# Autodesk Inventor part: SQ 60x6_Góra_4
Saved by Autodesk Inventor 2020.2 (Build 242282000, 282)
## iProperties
Created: 2006-08
Part Number: SQ 60x6_Góra_4
Material: Ogólny
Document SubType Name: Modeling
Designer: F.Stasiak
Manufacturer: Standard
Standards Organization: Custom
Stock Number: DIN EN 10210-2 SQ 60x6
Density: 1 g/cm^3
Appearance: Domyślna
Manager: www.cadconsulting.pl
Company: Fabian Stasiak CAD Consulting
G_L: 1000,0 mm
G_W: 60,000 mm
G_H: 60,000 mm
AFG_Item: 60 x 60 x 6
Author: F.Stasiak
Subject: Zbiór ćwiczeń. Autodesk Inventor 2020. Kurs podstawowy
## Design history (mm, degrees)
sketch "AFG_Detailed"
  geometry: L1 (48, 54)-(12, 54); L2 (6, 48)-(6, 12); L3 (12, 6)-(48, 6); L4 (54, 12)-(54, 48); L5 (48, 60)-(12, 60); L6 (0, 48)-(0, 12); L7 (12, 0)-(48, 0); L8 (60, 12)-(60, 48); A1 r 6 centre (48, 48) between (54, 48) and (48, 54); A2 r 12 centre (48, 48) between (60, 48) and (48, 60); A3 r 6 centre (48, 12) between (48, 6) and (54, 12); A4 r 12 centre (48, 12) between (48, 0) and (60, 12); A5 r 12 centre (12, 12) between (0, 12) and (12, 0); A6 r 6 centre (12, 12) between (6, 12) and (12, 6); A7 r 6 centre (12, 48) between (12, 54) and (6, 48); A8 r 12 centre (12, 48) between (12, 60) and (0, 48); 4 further points
  constraints: 16 end point, 16 point on circle, 16 tangent, 8 centre point, 6 point on line, 4 parallel, 2 perpendicular, 1 vertical
  dimensions: "d15" = 60 distance of point (0, 0) point (60, 0) (= GEO_B); "d16" = 6 distance between parallel lines of L7 L3 (= GEO_S); "d17" = 6 distance between parallel lines of L8 L4 (= GEO_S); "d18" = 6 distance between parallel lines of L5 L1 (= GEO_S); "d19" = 6 distance between parallel lines of L6 L2 (= GEO_S); "d20" = 30 distance from line of point (30, 30) L7 (= 0.5 x GEO_H); "d30" = 6 radius of A1 (= GEO_R1 - GEO_S); "GEO_R1" = 12 radius of A2; "d32" = 6 radius of A3 (= GEO_R1 - GEO_S); "d33" = 12 radius of A4 (= GEO_R1); "d34" = 12 radius of A5 (= GEO_R1); "d35" = 6 radius of A6 (= GEO_R1 - GEO_S); "d36" = 6 radius of A7 (= GEO_R1 - GEO_S); "d37" = 12 radius of A8 (= GEO_R1); "d38" = 30 distance from line of L6 point (30, 30) (= 0.5 x GEO_B); "d39" = 60 distance between parallel lines of L7 L5 (= GEO_H)
sketch "AFG_Medium"
  geometry: L1 (54, 54)-(6, 54); L2 (6, 54)-(6, 6); L3 (6, 6)-(54, 6); L4 (54, 6)-(54, 54); L5 (60, 60)-(0, 60); L6 (0, 60)-(0, 0); L7 (0, 0)-(60, 0); L8 (60, 0)-(60, 60); 1 further point
  constraints: 16 end point, 4 parallel, 2 perpendicular, 1 vertical
  dimensions: "GEO_B" = 60 distance of L6.end L7.end; "GEO_S" = 6 distance between parallel lines of L7 L3; "d5" = 6 distance between parallel lines of L8 L4 (= GEO_S); "d6" = 6 distance between parallel lines of L5 L1 (= GEO_S); "d7" = 6 distance between parallel lines of L6 L2 (= GEO_S); "d12" = 30 distance from line of point (30, 30) L7 (= 0.5 x GEO_H); "d40" = 60 distance between parallel lines of L7 L5 (= GEO_H); "d41" = 30 distance from line of L6 point (30, 30) (= 0.5 x GEO_B)
sketch "AFG_Simplified"
  geometry: L1 (60, 60)-(0, 60); L2 (0, 60)-(0, 0); L3 (0, 0)-(60, 0); L4 (60, 0)-(60, 60); 1 further point
  constraints: 8 end point, 2 parallel, 1 perpendicular, 1 vertical
  dimensions: "d23" = 60 distance of L2.end L3.end (= GEO_B); "d28" = 30 distance from line of point (30, 30) L3 (= 0.5 x GEO_H); "d42" = 60 distance between parallel lines of L3 L1 (= GEO_H); "d43" = 30 distance from line of point (30, 30) L2 (= 0.5 x GEO_B)
derived "Szkielet podstawy.ipt"
  sketch "Szkic1"
    geometry: L1 (0, 0)-(1500, 0) reference; L2 (1500, 0)-(1500, 1000) reference; L3 (1500, 1000)-(0, 1000) reference; L4 (0, 1000)-(0, 0) reference
  sketch "Szkic2"
    geometry: L1 (0, 1000)-(0, 0) reference; L2 (0, 0)-(1500, 0) reference; L3 (1500, 0)-(1500, 1000) reference; L4 (500, 1000)-(1500, 1000) reference; L5 (1500, 1000)-(1500, 0) reference; L6 (1500, 0)-(500, 0) reference; L7 (500, 0)-(500, 1000) reference; L8 (1500, 1000)-(0, 1000) reference
node "AFG_StartWorkPoint_SQ 60x6_Góra_4"
node "AFG_EndWorkPoint_SQ 60x6_Góra_4"
node "AFG_HelpAxis"
node "AFG_HelpStart"
node "AFG_HelpEnd"
node "AFG_Midplane"
  node "AFG_Startplane"
  node "AFG_EndPlane"
node "AFG_Profile_AxisX_for_External_Matrix"
extrude "AFG_Detailed_SQ 60x6_Góra_4" join sketch "AFG_Detailed" stored distance "d49" = 0.13; taper "d50" = 0 deg
extrude "AFG_Simplified_SQ 60x6_Góra_4" join sketch "AFG_Simplified" stored distance "d51" = 0.13; taper "d52" = 0 deg
node "AFG_StartWorkPoint_SQ 60x6_Góra_3"
node "AFG_EndWorkPoint_SQ 60x6_Góra_3"
node "AFG_STARTCUTPLANE_SQ 60x6_Góra_4"
node "AFG_StartWorkPoint_SQ 60x6_Góra_1"
node "AFG_EndWorkPoint_SQ 60x6_Góra_1"
node "AFG_ENDCUTPLANE_SQ 60x6_Góra_4"
node "Bryła1"
node "Korpusy bryłowe"
node "Korpusy powierzchniowe"
other parameters: "GEO_H" = 60, "AFG_Origin_X" = 0 (= 0 x GEO_B) [user parameter], "AFG_Origin_Y" = 0 (= 0 x GEO_H) [user parameter], "AFG_IP_X2" = 0 (= 0 x GEO_B) [user parameter], "AFG_IP_Y4" = 0 (= 0 x GEO_H) [user parameter], "AFG_IP_X6" = 0 (= 0 x GEO_B) [user parameter], "AFG_IP_Y8" = 0 (= 0 x GEO_H) [user parameter], "d47" = 0, "d48" = 0, "G_L" = 1000 [user parameter], "d55" = 0, "d58" = 0
